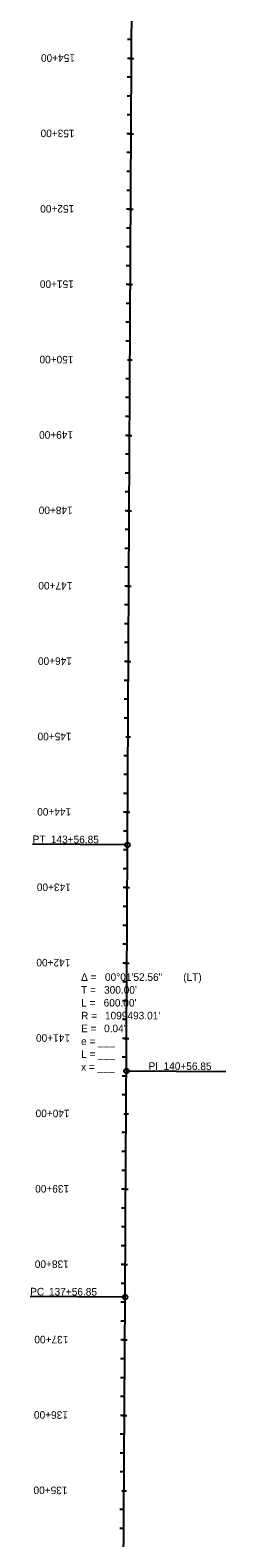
# Model space of a CAD drawing. Extents: x 23417911 to 23421158, y 6737892 to 6791804.
# Drawn here: x 23418152 to 23418412, y 6739912 to 6741912 of the extents above; entities that cross this region are included whole.
import ezdxf

# ---------------------------------------------------------------- set-up
doc = ezdxf.new("R2010")
doc.units = 0
for name, color, linetype in [('Alignment', 7, 'Continuous'), ('TextAlignment', 7, 'Continuous'), ('TextAlignmentLrg', 7, 'Continuous'), ('TextAlignmentSml', 7, 'Continuous')]:
    doc.layers.add(name, color=color, linetype=linetype)

msp = doc.modelspace()

# ---------------------------------------------------------------- linework, layer by layer
at = {"layer": 'Alignment'}
for p, q in [((23418281, 6740831.6), (23418291.3, 6742864.4)), ((23418281, 6740831.6), (23418291.3, 6742864.4)), ((23418264.8, 6737894.7), (23418277.8, 6740231.7))]:
    msp.add_line(p, q, dxfattribs=at)
msp.add_arc((22318802, 6746374.9), 1099493, 359.6798686, 359.7111352, dxfattribs=at)
msp.add_arc((22318802, 6746374.9), 1099493, 359.6798686, 359.7111352, dxfattribs=at)
at = {"layer": 'TextAlignment'}
for p, q in [((23418281, 6740831.6), (23418155, 6740832.3)), ((23418155, 6740832.3), (23418155, 6740832.3)), ((23418279.5, 6740531.6), (23418411.5, 6740530.9)), ((23418411.5, 6740530.9), (23418411.5, 6740530.9)), ((23418277.8, 6740231.7), (23418151.8, 6740232.4)), ((23418151.8, 6740232.4), (23418151.8, 6740232.4))]:
    msp.add_line(p, q, dxfattribs=at)
for centre in [(23418281, 6740831.6), (23418279.5, 6740531.6), (23418277.8, 6740231.7)]:
    msp.add_circle(centre, 3.12, dxfattribs=at)
at = {"layer": 'TextAlignmentLrg'}
for p, q in [((23418286.3, 6741874.8), (23418280.8, 6741874.8)), ((23418285.8, 6741774.8), (23418280.3, 6741774.8)), ((23418285.3, 6741674.8), (23418279.8, 6741674.8)), ((23418284.8, 6741574.8), (23418279.3, 6741574.8)), ((23418281.2, 6741474.8), (23418287.3, 6741474.8)), ((23418283.8, 6741374.8), (23418278.3, 6741374.8)), ((23418283.2, 6741274.8), (23418277.8, 6741274.8)), ((23418282.7, 6741174.8), (23418277.3, 6741174.8)), ((23418282.2, 6741074.8), (23418276.8, 6741074.8)), ((23418278.7, 6740974.8), (23418284.8, 6740974.8)), ((23418281.2, 6740874.8), (23418275.8, 6740874.8)), ((23418280.7, 6740774.8), (23418275.3, 6740774.8)), ((23418280.2, 6740674.8), (23418274.8, 6740674.8)), ((23418279.7, 6740574.8), (23418274.2, 6740574.8)), ((23418276.1, 6740474.8), (23418282.2, 6740474.8)), ((23418278.6, 6740374.8), (23418273.2, 6740374.8)), ((23418278.1, 6740274.8), (23418272.6, 6740274.8)), ((23418277.5, 6740174.8), (23418272, 6740174.8)), ((23418277, 6740074.8), (23418271.5, 6740074.8)), ((23418273.3, 6739974.8), (23418279.5, 6739974.8))]:
    msp.add_line(p, q, dxfattribs=at)
at = {"layer": 'TextAlignmentSml'}
for p, q in [((23418286.4, 6741899.8), (23418280.9, 6741899.8)), ((23418283.2, 6741874.8), (23418289.3, 6741874.8)), ((23418286.1, 6741849.8), (23418280.7, 6741849.8)), ((23418286, 6741824.8), (23418280.6, 6741824.8)), ((23418285.9, 6741799.8), (23418280.4, 6741799.8)), ((23418282.7, 6741774.8), (23418288.8, 6741774.8)), ((23418285.6, 6741749.8), (23418280.2, 6741749.8)), ((23418285.5, 6741724.8), (23418280.1, 6741724.8)), ((23418285.4, 6741699.8), (23418279.9, 6741699.8)), ((23418282.2, 6741674.8), (23418288.3, 6741674.8)), ((23418285.1, 6741649.8), (23418279.7, 6741649.8)), ((23418285, 6741624.8), (23418279.6, 6741624.8)), ((23418284.9, 6741599.8), (23418279.4, 6741599.8)), ((23418281.7, 6741574.8), (23418287.8, 6741574.8)), ((23418284.6, 6741549.8), (23418279.2, 6741549.8)), ((23418284.5, 6741524.8), (23418279, 6741524.8)), ((23418284.4, 6741499.8), (23418278.9, 6741499.8)), ((23418281.2, 6741474.8), (23418287.3, 6741474.8)), ((23418284.1, 6741449.8), (23418278.7, 6741449.8)), ((23418284, 6741424.8), (23418278.5, 6741424.8)), ((23418283.9, 6741399.8), (23418278.4, 6741399.8)), ((23418280.7, 6741374.8), (23418286.8, 6741374.8)), ((23418283.6, 6741349.8), (23418278.2, 6741349.8)), ((23418283.5, 6741324.8), (23418278, 6741324.8)), ((23418283.4, 6741299.8), (23418277.9, 6741299.8)), ((23418280.2, 6741274.8), (23418286.3, 6741274.8)), ((23418283.1, 6741249.8), (23418277.7, 6741249.8)), ((23418283, 6741224.8), (23418277.5, 6741224.8)), ((23418282.9, 6741199.8), (23418277.4, 6741199.8)), ((23418279.7, 6741174.8), (23418285.8, 6741174.8)), ((23418282.6, 6741149.8), (23418277.2, 6741149.8)), ((23418282.5, 6741124.8), (23418277, 6741124.8)), ((23418282.4, 6741099.8), (23418276.9, 6741099.8)), ((23418279.2, 6741074.8), (23418285.3, 6741074.8)), ((23418282.1, 6741049.8), (23418276.7, 6741049.8)), ((23418282, 6741024.8), (23418276.5, 6741024.8)), ((23418281.9, 6740999.8), (23418276.4, 6740999.8)), ((23418278.7, 6740974.8), (23418284.8, 6740974.8)), ((23418281.6, 6740949.8), (23418276.2, 6740949.8)), ((23418281.5, 6740924.8), (23418276, 6740924.8)), ((23418281.4, 6740899.8), (23418275.9, 6740899.8)), ((23418278.2, 6740874.8), (23418284.3, 6740874.8)), ((23418281.1, 6740849.8), (23418275.6, 6740849.8)), ((23418281, 6740824.8), (23418275.5, 6740824.8)), ((23418280.9, 6740799.8), (23418275.4, 6740799.8)), ((23418277.7, 6740774.8), (23418283.8, 6740774.8)), ((23418280.6, 6740749.8), (23418275.1, 6740749.8)), ((23418280.5, 6740724.8), (23418275, 6740724.8)), ((23418280.3, 6740699.8), (23418274.9, 6740699.8)), ((23418277.2, 6740674.8), (23418283.3, 6740674.8)), ((23418280.1, 6740649.8), (23418274.6, 6740649.8)), ((23418280, 6740624.8), (23418274.5, 6740624.8)), ((23418279.8, 6740599.8), (23418274.4, 6740599.8)), ((23418276.6, 6740574.8), (23418282.8, 6740574.8)), ((23418279.6, 6740549.8), (23418274.1, 6740549.8)), ((23418279.4, 6740524.8), (23418274, 6740524.8)), ((23418279.3, 6740499.8), (23418273.8, 6740499.8)), ((23418276.1, 6740474.8), (23418282.2, 6740474.8)), ((23418279, 6740449.8), (23418273.6, 6740449.8)), ((23418278.9, 6740424.8), (23418273.4, 6740424.8)), ((23418278.8, 6740399.8), (23418273.3, 6740399.8)), ((23418275.6, 6740374.8), (23418281.7, 6740374.8)), ((23418278.5, 6740349.8), (23418273, 6740349.8)), ((23418278.3, 6740324.8), (23418272.9, 6740324.8)), ((23418278.2, 6740299.8), (23418272.7, 6740299.8)), ((23418275, 6740274.8), (23418281.1, 6740274.8)), ((23418277.9, 6740249.8), (23418272.5, 6740249.8)), ((23418277.8, 6740224.8), (23418272.3, 6740224.8)), ((23418277.6, 6740199.8), (23418272.2, 6740199.8)), ((23418274.4, 6740174.8), (23418280.6, 6740174.8)), ((23418277.4, 6740149.8), (23418271.9, 6740149.8)), ((23418277.2, 6740124.8), (23418271.8, 6740124.8)), ((23418277.1, 6740099.8), (23418271.6, 6740099.8)), ((23418273.9, 6740074.8), (23418280, 6740074.8)), ((23418276.8, 6740049.8), (23418271.4, 6740049.8)), ((23418276.7, 6740024.8), (23418271.2, 6740024.8)), ((23418276.5, 6739999.8), (23418271.1, 6739999.8)), ((23418273.3, 6739974.8), (23418279.5, 6739974.8)), ((23418276.3, 6739949.8), (23418270.8, 6739949.8)), ((23418276.1, 6739924.8), (23418270.7, 6739924.8))]:
    msp.add_line(p, q, dxfattribs=at)

# ---------------------------------------------------------------- texts
at = {"layer": 'TextAlignment'}
for s, rotation, p in [('PT', 359.7111, (23418155, 6740834)), ('143+56.85', 359.7111, (23418179.3, 6740833.9)), ('PI ', 359.6955, (23418308.8, 6740533.2)), ('140+56.85', 359.6955, (23418328.8, 6740533.1)), ('PC', 359.6799, (23418151.8, 6740234)), ('137+56.85', 359.6799, (23418176.8, 6740233.9))]:
    msp.add_text(s, height=10.02, rotation=rotation, dxfattribs=at).set_placement(p)
for s, p in [('T = ', (23418219.4, 6740634.2)), ('Δ = ', (23418219.4, 6740651.2)), ("300.00'", (23418249.9, 6740634.2)), ('00°01\'52.56"', (23418251.1, 6740651.2)), (' (LT)', (23418351.2, 6740651.2)), ('L = ', (23418219.4, 6740617.1)), ("600.00'", (23418249.3, 6740617.1)), ('R = ', (23418219.4, 6740600.1)), ("1099493.01'", (23418251.1, 6740600.1)), ('E = ', (23418219.4, 6740583.1)), ("0.04'", (23418249.9, 6740583.1)), ('e = ___ ', (23418219.4, 6740566)), ('L = ___', (23418219.4, 6740549)), ('x = ___', (23418219.4, 6740532))]:
    msp.add_text(s, height=10.02, dxfattribs=at).set_placement(p)
at = {"layer": 'TextAlignmentLrg'}
for s, rotation, p in [('150+00', 179.7111, (23418209.3, 6741480.2)), ('145+00', 179.7111, (23418206.8, 6740980.2)), ('140+00', 179.6925, (23418204.2, 6740480.2)), ('135+00', 179.6799, (23418201.4, 6739980.2))]:
    msp.add_text(s, height=10.02, rotation=rotation, dxfattribs=at).set_placement(p)
at = {"layer": 'TextAlignmentSml'}
for s, rotation, p in [('154+00', 179.7111, (23418211.3, 6741880.2)), ('153+00', 179.7111, (23418210.8, 6741780.2)), ('152+00', 179.7111, (23418210.3, 6741680.2)), ('151+00', 179.7111, (23418209.8, 6741580.2)), ('150+00', 179.7111, (23418209.3, 6741480.2)), ('149+00', 179.7111, (23418208.8, 6741380.2)), ('148+00', 179.7111, (23418208.3, 6741280.2)), ('147+00', 179.7111, (23418207.8, 6741180.2)), ('146+00', 179.7111, (23418207.3, 6741080.2)), ('145+00', 179.7111, (23418206.8, 6740980.2)), ('144+00', 179.7111, (23418206.3, 6740880.2)), ('143+00', 179.7082, (23418205.8, 6740780.2)), ('142+00', 179.703, (23418205.2, 6740680.2)), ('141+00', 179.6978, (23418204.7, 6740580.2)), ('140+00', 179.6925, (23418204.2, 6740480.2)), ('139+00', 179.6873, (23418203.6, 6740380.2)), ('138+00', 179.6821, (23418203.1, 6740280.2)), ('137+00', 179.6799, (23418202.5, 6740180.2)), ('136+00', 179.6799, (23418202, 6740080.2)), ('135+00', 179.6799, (23418201.4, 6739980.2))]:
    msp.add_text(s, height=10.02, rotation=rotation, dxfattribs=at).set_placement(p)

doc.saveas('drawing.dxf')
